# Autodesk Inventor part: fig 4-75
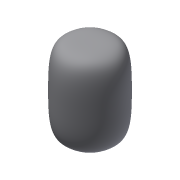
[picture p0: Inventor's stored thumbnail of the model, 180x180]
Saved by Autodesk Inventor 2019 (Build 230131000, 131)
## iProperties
Created: 2012-07
Part Number: fig 4-75
Material: Generic
Document SubType Name: Modeling
Designer: CADCIM
Density: 1 g/cm^3
Appearance: Default
Author: CADCIM
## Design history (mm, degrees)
feature "Form1"
body "Solid1"
body "Solid2"
